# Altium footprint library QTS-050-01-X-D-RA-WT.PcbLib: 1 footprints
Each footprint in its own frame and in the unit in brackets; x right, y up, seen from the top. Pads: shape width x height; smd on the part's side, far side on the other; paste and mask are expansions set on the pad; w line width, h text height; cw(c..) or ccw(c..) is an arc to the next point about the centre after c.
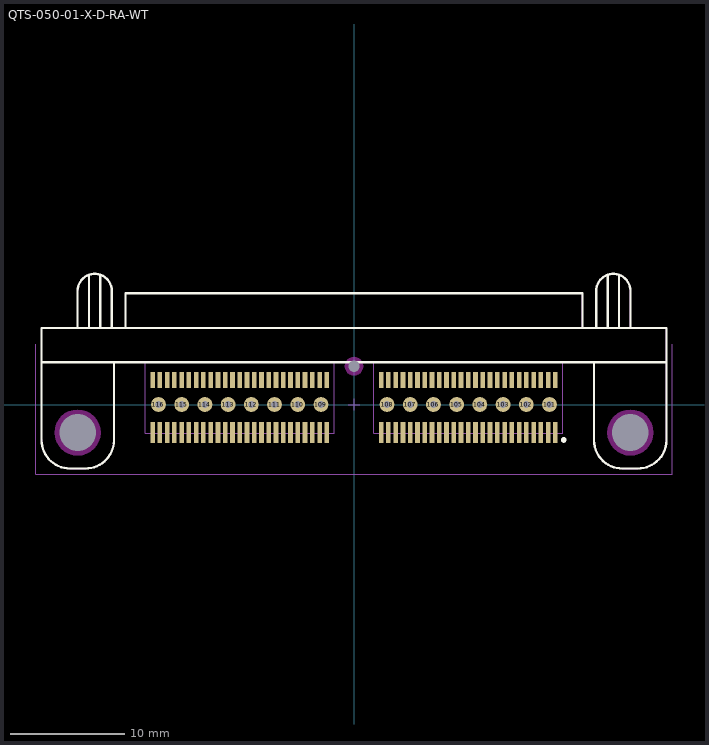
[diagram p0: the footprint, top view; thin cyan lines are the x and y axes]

## QTS-050-01-X-D-RA-WT [mm] "0.635mm pitch, 100 pin, high speed terminal strip; r/a, w/weld tabs"
height 9.42
pads (119):
  rect 0.4x1.8 smd mask+0: 1(17.621,-2.451) 3(16.986,-2.451) 5(16.351,-2.451) 7(15.716,-2.451) 9(15.081,-2.451) 11(14.446,-2.451) 13(13.811,-2.451) 15(13.176,-2.451) 17(12.541,-2.451) 19(11.906,-2.451) 21(11.271,-2.451) 23(10.636,-2.451) 25(10.001,-2.451) 27(9.366,-2.451) 29(8.731,-2.451) 31(8.096,-2.451) 33(7.461,-2.451) 35(6.826,-2.451) 37(6.191,-2.451) 39(5.556,-2.451) 41(4.921,-2.451) 43(4.286,-2.451) 45(3.651,-2.451) 47(3.016,-2.451) 49(2.381,-2.451) 51(-2.381,-2.451) 53(-3.016,-2.451) 55(-3.651,-2.451) 57(-4.286,-2.451) 59(-4.921,-2.451) 61(-5.556,-2.451) 63(-6.191,-2.451) 65(-6.826,-2.451) 67(-7.461,-2.451) 69(-8.096,-2.451) 71(-8.731,-2.451) 73(-9.366,-2.451) 75(-10.001,-2.451) 77(-10.636,-2.451) 79(-11.271,-2.451) 81(-11.906,-2.451) 83(-12.541,-2.451) 85(-13.176,-2.451) 87(-13.811,-2.451) 89(-14.446,-2.451) 91(-15.081,-2.451) 93(-15.716,-2.451) 95(-16.351,-2.451) 97(-16.986,-2.451) 99(-17.621,-2.451)
  rect 0.4x1.4 smd mask+0: 2(17.621,2.159) 4(16.986,2.159) 6(16.351,2.159) 8(15.716,2.159) 10(15.081,2.159) 12(14.446,2.159) 14(13.811,2.159) 16(13.176,2.159) 18(12.541,2.159) 20(11.906,2.159) 22(11.271,2.159) 24(10.636,2.159) 26(10.001,2.159) 28(9.366,2.159) 30(8.731,2.159) 32(8.096,2.159) 34(7.461,2.159) 36(6.826,2.159) 38(6.191,2.159) 40(5.556,2.159) 42(4.921,2.159) 44(4.286,2.159) 46(3.651,2.159) 48(3.016,2.159) 50(2.381,2.159) 52(-2.381,2.159) 54(-3.016,2.159) 56(-3.651,2.159) 58(-4.286,2.159) 60(-4.921,2.159) 62(-5.556,2.159) 64(-6.191,2.159) 66(-6.826,2.159) 68(-7.461,2.159) 70(-8.096,2.159) 72(-8.731,2.159) 74(-9.366,2.159) 76(-10.001,2.159) 78(-10.636,2.159) 80(-11.271,2.159) 82(-11.906,2.159) 84(-12.541,2.159) 86(-13.176,2.159) 88(-13.811,2.159) 90(-14.446,2.159) 92(-15.081,2.159) 94(-15.716,2.159) 96(-16.351,2.159) 98(-16.986,2.159) 100(-17.621,2.159)
  round 1.3 hole 0.6 mask+0: 101(17.113,0) 102(15.081,0) 103(13.049,0) 104(11.017,0) 105(8.985,0) 106(6.953,0) 107(4.921,0) 108(2.889,0) 109(-2.89,0) 110(-4.922,0) 111(-6.954,0) 112(-8.986,0) 113(-11.018,0) 114(-13.05,0) 115(-15.082,0) 116(-17.114,0)
  round 1 hole 3.2 unplated mask+0: 117(24.193,-2.451) 118(-24.193,-2.451)
  round 0.5 hole 1 unplated mask+0: 119(0,3.353)
Top Overlay:
  circle w0.25: c18.35,-3.1 r0.125
  lines w0.2: -27.35,-3.126 ccw(c-24.867,-3.117) -24.867,-5.6 -23.517,-5.6 ccw(c-23.5,-3.1) -21,-3.126 -21,3.7 ; -27.35,-3.126 -27.35,3.693 ; -24.2,6.7 -24.2,9.943 cw(c-22.7,9.943) -21.2,9.943 -21.2,6.7 ; -23.2,6.7 -23.2,11.35 ; -22.2,6.7 -22.2,11.35 ; -20,6.7 -20,9.75 20.001,9.75 20.001,6.7 ; 21,3.693 21,-3.15 ccw(c23.489,-3.111) 23.502,-5.6 ; 21.201,6.7 21.201,9.943 cw(c22.701,9.943) 24.201,9.943 24.202,6.7 ; 22.201,6.7 22.201,11.35 ; 23.202,6.7 23.202,11.35 ; 23.5,-5.6 24.85,-5.6 ccw(c24.85,-3.099) 27.35,-3.152 ; 27.35,-3.15 27.35,3.7 ; 27.35,3.7 27.35,6.7 -27.35,6.7 -27.35,3.7 27.35,3.7
Keep-Out Layer:
  pour cut-out: -22.183,-2.451 -22.222,-2.059 -22.336,-1.682 -22.522,-1.334 -22.772,-1.03 -23.076,-0.78 -23.424,-0.594 -23.801,-0.48 -24.193,-0.441 -24.585,-0.48 -24.962,-0.594 -25.31,-0.78 -25.614,-1.03 -25.864,-1.334 -26.05,-1.682 -26.164,-2.059 -26.203,-2.451 -26.164,-2.843 -26.05,-3.22 -25.864,-3.568 -25.614,-3.872 -25.31,-4.122 -24.962,-4.308 -24.585,-4.422 -24.193,-4.461 -23.801,-4.422 -23.424,-4.308 -23.076,-4.122 -22.772,-3.872 -22.522,-3.568 -22.336,-3.22 -22.222,-2.843
  pour cut-out: 26.203,-2.451 26.164,-2.059 26.05,-1.682 25.864,-1.334 25.614,-1.03 25.31,-0.78 24.962,-0.594 24.585,-0.48 24.193,-0.441 23.801,-0.48 23.424,-0.594 23.076,-0.78 22.772,-1.03 22.522,-1.334 22.336,-1.682 22.222,-2.059 22.183,-2.451 22.222,-2.843 22.336,-3.22 22.522,-3.568 22.772,-3.872 23.076,-4.122 23.424,-4.308 23.801,-4.422 24.193,-4.461 24.585,-4.422 24.962,-4.308 25.31,-4.122 25.614,-3.872 25.864,-3.568 26.05,-3.22 26.164,-2.843
  pour cut-out: 0.807,3.353 0.779,3.562 0.699,3.756 0.571,3.924 0.403,4.052 0.209,4.132 0,4.16 -0.209,4.132 -0.403,4.052 -0.571,3.924 -0.699,3.756 -0.779,3.562 -0.807,3.353 -0.779,3.144 -0.699,2.95 -0.571,2.782 -0.403,2.654 -0.209,2.574 0,2.546 0.209,2.574 0.403,2.654 0.571,2.782 0.699,2.95 0.779,3.144
Mechanical 12:
  lines w0.001: -27.35,-3.1 -27.35,6.7 -20,6.7 -20,9.75 20,9.75 20,6.7 27.35,6.7 27.35,-3.1 ; -24.85,-5.6 -23.5,-5.6 ; -21,-3.1 -21,3.7 -18.25,3.7 -18.25,-2.5 -1.75,-2.5 -1.75,3.7 1.75,3.7 1.75,-2.5 18.25,-2.5 18.25,3.7 21,3.7 21,-3.1 ; 23.5,-5.6 24.85,-5.6
Mechanical 13:
  lines w0.1: -27.35,3.693 -27.35,-3.126 ccw(c-24.85,-3.1) -24.867,-5.6 -23.517,-5.6 ccw(c-23.496,-3.104) -21,-3.126 -21,3.7 ; -24.2,6.7 -24.2,9.943 cw(c-22.7,9.943) -21.2,9.943 -21.2,6.7 ; -23.2,6.7 -23.2,11.35 ; -22.2,6.7 -22.2,11.35 ; -20,6.7 -20,9.75 20.001,9.75 20.001,6.7 ; -18.25,3.7 -18.25,-2.5 -1.75,-2.5 -1.75,3.693 ; 1.75,3.693 1.75,-2.5 18.25,-2.5 18.25,3.693 ; 21,3.693 21,-3.15 ccw(c23.489,-3.111) 23.502,-5.6 ; 21.201,6.7 21.201,9.943 cw(c22.701,9.943) 24.201,9.943 24.202,6.7 ; 22.201,6.7 22.201,11.35 ; 23.202,6.7 23.202,11.35 ; 23.5,-5.6 24.85,-5.6 ccw(c24.85,-3.099) 27.35,-3.152 ; 27.35,-3.15 27.35,3.7 ; 27.35,3.7 27.35,6.7 -27.35,6.7 -27.35,3.7 27.35,3.7
  text ".Designator" at 0,0 h1.52
Mechanical 15:
  lines w0.05: -27.85,5.296 -27.85,-6.1 27.85,-6.1 27.85,5.296 ; -0.5,0 0.5,0 ; 0,-0.5 0,0.5
Mechanical 16:
  lines w0.001: -27.35,-3.1 ccw(c-24.85,-3.1) -24.85,-5.6 ; -23.5,-5.6 ccw(c-23.5,-3.1) -21,-3.1 ; 21,-3.1 ccw(c23.5,-3.1) 23.5,-5.6 ; 24.85,-5.6 ccw(c24.85,-3.1) 27.35,-3.1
